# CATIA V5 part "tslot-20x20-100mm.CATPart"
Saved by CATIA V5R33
Part number: tslot-20x20-100mm
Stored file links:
  C:\Users\Ryzen5700u\Desktop\robot_cicloidale_singolo\Assieme_robot_cicloidale_singolo\tslot-20x20-100mm.CATPart

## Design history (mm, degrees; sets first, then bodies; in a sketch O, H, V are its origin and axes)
Body1 "Solido1" (main body)
  Solid1: solid without history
